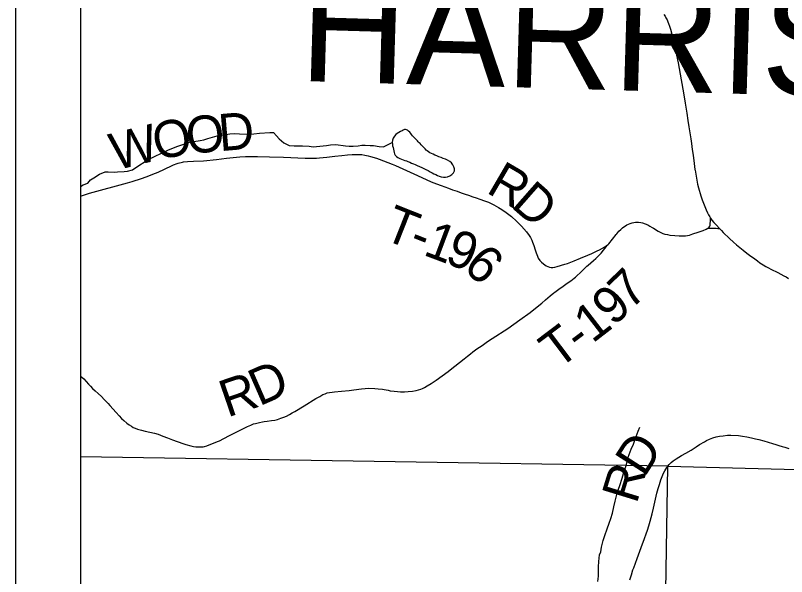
# Model space of a CAD drawing. Extents: x -19.9 to 41.9, y 0 to 32.3.
# Drawn here: x 2 to 3.184, y 16.729 to 17.59 of the extents above; entities that cross this region are included whole.
import ezdxf

# ---------------------------------------------------------------- set-up
doc = ezdxf.new("R2010")
doc.units = 0
for name, color, linetype in [('GM_X_Corporation', 7, 'Continuous'), ('GM_X_County_Road', 7, 'Continuous'), ('GM_X_County_Text', 7, 'Continuous'), ('GM_X_Minor_River', 7, 'Continuous'), ('GM_X_Township_Road', 7, 'Continuous'), ('GM_X_Township_Road_Text', 7, 'Continuous'), ('SH_Data', 7, 'Continuous')]:
    doc.layers.add(name, color=color, linetype=linetype)

msp = doc.modelspace()

# ---------------------------------------------------------------- linework, layer by layer
at = {"layer": 'GM_X_Corporation'}
for points in [[(2.1, 17.918), (2.1, 14.1), (8.9, 14.1), (8.9, 17.8974), (7.9072, 17.9171), (7.5529, 17.9242), (7.3858, 17.9277), (6.9468, 17.937), (6.7, 17.9422), (6.3069, 17.9505), (6.2497, 17.9517), (6.2397, 17.9517), (5.9048, 17.9534), (5.761, 17.9543), (5.4954, 17.9559), (5.0257, 17.9637), (5.0192, 17.8403), (4.9169, 17.8392), (4.2613, 17.8672), (3.984, 17.879), (3.7505, 17.884), (2.973, 17.9007), (2.4715, 17.9106)], [(2.1, 16.9124), (2.1, 15.8858), (2.9854, 15.8784), (3.0015, 16.8981)], [(3.0015, 16.8981), (4.0122, 16.8721), (3.9969, 15.8607), (2.9854, 15.8784)]]:
    msp.add_lwpolyline(points, close=True, dxfattribs=at)
msp.add_lwpolyline([(2.1, 17.918), (2.1, 14.1), (7.8246, 14.1), (7.8518, 15.3043), (7.854, 15.4058), (7.8702, 16.1679), (7.8776, 16.5173), (7.9012, 17.4524), (7.9072, 17.9171)], dxfattribs=at)
at = {"layer": 'GM_X_County_Road'}
msp.add_lwpolyline([(2.9956, 17.591), (2.9973, 17.5884), (2.9986, 17.586), (3.0004, 17.5828), (3.0017, 17.5801), (3.0028, 17.5774), (3.0043, 17.5731), (3.0058, 17.5684), (3.0071, 17.5632), (3.0092, 17.5543), (3.0138, 17.5334), (3.0173, 17.517), (3.0223, 17.4907), (3.0257, 17.471), (3.0283, 17.4552), (3.0307, 17.4396), (3.0325, 17.4286), (3.0339, 17.4187), (3.0348, 17.4126), (3.0368, 17.4003), (3.0379, 17.3931), (3.0392, 17.3842), (3.0404, 17.3751), (3.0421, 17.3627), (3.0433, 17.3534), (3.0434, 17.3524), (3.0466, 17.334), (3.0472, 17.3306), (3.0486, 17.3252), (3.0523, 17.313), (3.0544, 17.3069), (3.0574, 17.299), (3.0605, 17.2913), (3.0627, 17.2866), (3.0643, 17.2835), (3.0659, 17.2808), (3.0673, 17.2787), (3.0694, 17.2755), (3.0723, 17.272), (3.0756, 17.2681), (3.0809, 17.2626), (3.0839, 17.2595), (3.0868, 17.2566), (3.0964, 17.2473), (3.1026, 17.2416), (3.1072, 17.2377), (3.1172, 17.2295), (3.123, 17.225), (3.129, 17.2205), (3.133, 17.2176), (3.1392, 17.213), (3.1431, 17.2102), (3.148, 17.207), (3.1523, 17.2044), (3.156, 17.2025), (3.1598, 17.2005), (3.1705, 17.1951), (3.1752, 17.1926), (3.1796, 17.1902), (3.1832, 17.1883), (3.1868, 17.1862)], dxfattribs=at)
at = {"layer": 'GM_X_Minor_River'}
for points in [[(2.1, 17.3273), (2.1042, 17.3295), (2.111, 17.3322), (2.1151, 17.3373), (2.1203, 17.3404), (2.1293, 17.3462), (2.1376, 17.3498), (2.1425, 17.3495), (2.1516, 17.3492), (2.1569, 17.3497), (2.1668, 17.3502), (2.172, 17.3507), (2.1796, 17.3527), (2.1848, 17.3566), (2.204, 17.3687), (2.2341, 17.3829), (2.2427, 17.3864), (2.2495, 17.3892), (2.2672, 17.3952), (2.2834, 17.3977), (2.2895, 17.399), (2.2955, 17.401), (2.3098, 17.405), (2.3163, 17.4062), (2.3291, 17.408), (2.3371, 17.4085), (2.3439, 17.4078), (2.3564, 17.4076), (2.3662, 17.4081), (2.3749, 17.409), (2.3904, 17.41)], [(2.3904, 17.41), (2.3961, 17.4101), (2.4007, 17.4052), (2.405, 17.4004), (2.4119, 17.394), (2.4202, 17.3899), (2.4282, 17.3897), (2.4407, 17.3895), (2.4509, 17.3889), (2.457, 17.3882), (2.4623, 17.3887), (2.4672, 17.3891), (2.4774, 17.39), (2.4835, 17.3909), (2.4918, 17.3914), (2.5066, 17.3897), (2.5123, 17.3891), (2.5187, 17.3892), (2.5263, 17.3897), (2.5316, 17.3905), (2.5372, 17.3906), (2.5448, 17.3903), (2.5497, 17.39), (2.5585, 17.3886), (2.5649, 17.3883), (2.5786, 17.3948)], [(2.9456, 16.9243), (2.9489, 16.9316), (2.9529, 16.9434), (2.9562, 16.9515), (2.9584, 16.9576)], [(2.8944, 16.7209), (2.8951, 16.7293), (2.895, 16.735), (2.8953, 16.7434), (2.8959, 16.7518), (2.8969, 16.7617), (2.8987, 16.7667), (2.8997, 16.7739), (2.9022, 16.7839), (2.9048, 16.7915), (2.9084, 16.8019), (2.9117, 16.8107), (2.9139, 16.8176), (2.9168, 16.826), (2.9185, 16.8355), (2.9207, 16.8443), (2.9246, 16.8585), (2.9279, 16.8684), (2.9315, 16.8795), (2.9337, 16.8868), (2.938, 16.9006), (2.9409, 16.912), (2.9456, 16.9243)]]:
    msp.add_lwpolyline(points, dxfattribs=at)
for points in [[(2.5805, 17.3846), (2.5832, 17.3751), (2.5927, 17.369), (2.6026, 17.3656), (2.6137, 17.3607), (2.627, 17.355), (2.64, 17.3481), (2.6507, 17.3432), (2.6636, 17.342), (2.6739, 17.3512), (2.6697, 17.3633), (2.6567, 17.3702), (2.6438, 17.3755), (2.6342, 17.3804), (2.6213, 17.393), (2.6098, 17.4051), (2.5972, 17.4146), (2.5937, 17.4126)], [(2.5937, 17.4126), (2.5839, 17.407), (2.5786, 17.3948), (2.5805, 17.3846)]]:
    msp.add_spline(points, degree=3, dxfattribs=at)
at = {"layer": 'GM_X_Township_Road'}
for points in [[(2.1, 17.3122), (2.1139, 17.3169), (2.1721, 17.3328), (2.1793, 17.3349), (2.1934, 17.3395), (2.2005, 17.342), (2.2153, 17.3476), (2.2194, 17.3494), (2.2396, 17.3588), (2.2429, 17.3603), (2.2481, 17.3623), (2.25, 17.3629), (2.2565, 17.3645), (2.258, 17.3648), (2.2642, 17.3653), (2.2734, 17.3659), (2.2887, 17.3668), (2.3085, 17.3686), (2.324, 17.3705), (2.3342, 17.3715), (2.3443, 17.3726), (2.3531, 17.3731), (2.364, 17.3734), (2.3718, 17.3732), (2.3903, 17.3729), (2.4114, 17.3723), (2.445, 17.3706), (2.4497, 17.3705), (2.4559, 17.3705), (2.4622, 17.3708), (2.467, 17.3712), (2.4781, 17.3723), (2.4906, 17.3737), (2.5011, 17.3748), (2.5098, 17.3757), (2.5168, 17.3763), (2.5228, 17.3765), (2.5318, 17.3761), (2.5365, 17.3755), (2.5415, 17.3744), (2.5453, 17.3734), (2.5542, 17.3705), (2.5584, 17.369), (2.5782, 17.3614), (2.5834, 17.3592), (2.6171, 17.3441), (2.6385, 17.3346), (2.6464, 17.3312), (2.6535, 17.3285), (2.6647, 17.3244), (2.6709, 17.3223), (2.6781, 17.3198), (2.6842, 17.3177), (2.6904, 17.3156), (2.6955, 17.3139), (2.7024, 17.3115), (2.7076, 17.3097), (2.713, 17.3078), (2.72, 17.3053), (2.7262, 17.3029), (2.7304, 17.3012), (2.7344, 17.2993), (2.7382, 17.2972), (2.7417, 17.2949), (2.7467, 17.2919), (2.7536, 17.2871), (2.7615, 17.2813), (2.7695, 17.2741), (2.777, 17.2662), (2.7846, 17.2578), (2.7889, 17.2521), (2.7907, 17.249), (2.7926, 17.245), (2.794, 17.2416), (2.7961, 17.2364), (2.7981, 17.23), (2.7993, 17.2256), (2.8013, 17.2204), (2.8028, 17.2172), (2.805, 17.2137), (2.8075, 17.2108), (2.8105, 17.2083), (2.8146, 17.2055), (2.8172, 17.2044), (2.82, 17.2035), (2.8224, 17.2031), (2.8249, 17.203), (2.828, 17.2034), (2.8318, 17.2043), (2.8435, 17.2078), (2.8474, 17.2091), (2.858, 17.2131), (2.8678, 17.217), (2.8788, 17.2217), (2.8851, 17.2244), (2.8929, 17.2282), (2.8968, 17.2302), (2.9051, 17.2348), (2.9077, 17.2366), (2.9099, 17.2381), (2.9106, 17.2388), (2.9111, 17.2394), (2.9222, 17.2533), (2.9234, 17.2547), (2.9266, 17.2584), (2.9296, 17.2614), (2.932, 17.2636), (2.9343, 17.2655), (2.9365, 17.2669), (2.9385, 17.2681), (2.944, 17.2704), (2.9468, 17.2713), (2.9494, 17.2719), (2.9522, 17.2722), (2.9546, 17.2723), (2.9568, 17.2722), (2.9601, 17.2718), (2.9627, 17.2712), (2.967, 17.2697), (2.9708, 17.2681), (2.974, 17.2665), (2.9774, 17.2645), (2.9795, 17.2632), (2.9868, 17.2586), (2.9898, 17.257), (2.9939, 17.2553), (2.9971, 17.2542), (3.0011, 17.2533), (3.0049, 17.2526), (3.0122, 17.2518), (3.0191, 17.2514), (3.029, 17.2516), (3.0317, 17.252), (3.0347, 17.2527), (3.04, 17.2543), (3.0484, 17.2572), (3.0558, 17.2599), (3.0607, 17.2618), (3.0633, 17.2631), (3.0641, 17.2636), (3.0653, 17.265), (3.066, 17.2665), (3.0664, 17.2678), (3.0667, 17.2699), (3.0671, 17.2747), (3.0673, 17.2787)], [(3.0633, 17.2631), (3.0648, 17.2632), (3.0678, 17.2634), (3.0738, 17.2633), (3.076, 17.2632), (3.0785, 17.2629), (3.0809, 17.2626)], [(2.5911, 17.0123), (2.5973, 17.0122), (2.6032, 17.0125), (2.6094, 17.0132), (2.6155, 17.0143), (2.6188, 17.0151), (2.6222, 17.0162), (2.625, 17.0172), (2.6279, 17.0186), (2.6323, 17.0211), (2.6383, 17.0249), (2.6459, 17.03), (2.6642, 17.0434), (2.6702, 17.0478), (2.6744, 17.0512), (2.6888, 17.0629), (2.6939, 17.0668), (2.6987, 17.0705), (2.7025, 17.0735), (2.7085, 17.0778), (2.7167, 17.0834), (2.725, 17.0891), (2.7321, 17.094), (2.756, 17.1095), (2.7744, 17.1223), (2.7904, 17.134), (2.7936, 17.1365), (2.8081, 17.1483), (2.814, 17.1533), (2.821, 17.1592), (2.8266, 17.1639), (2.8281, 17.1651), (2.8341, 17.1695), (2.8407, 17.1741), (2.8473, 17.1787), (2.854, 17.1834), (2.8555, 17.1846), (2.8578, 17.1864), (2.8598, 17.1882), (2.8618, 17.19), (2.8674, 17.1954), (2.8725, 17.2004), (2.8773, 17.2049), (2.8791, 17.2066), (2.8876, 17.2135), (2.8911, 17.2166), (2.8943, 17.2198), (2.8969, 17.2224), (2.8993, 17.2251), (2.9087, 17.2366), (2.9099, 17.2381)], [(2.1, 17.0363), (2.1022, 17.0346), (2.105, 17.0318), (2.1124, 17.0239), (2.1152, 17.0209), (2.1185, 17.0174), (2.1225, 17.0138), (2.127, 17.0095), (2.1322, 17.0047), (2.1363, 17.0005), (2.1398, 16.9967), (2.1425, 16.9939), (2.145, 16.9912), (2.1545, 16.9804), (2.1593, 16.9751), (2.163, 16.9713), (2.1666, 16.968), (2.1713, 16.9642), (2.1747, 16.9616), (2.1783, 16.9591), (2.1809, 16.9575), (2.1839, 16.9562), (2.1874, 16.955), (2.1935, 16.9534), (2.1991, 16.9519), (2.2062, 16.9501), (2.2135, 16.9484), (2.2192, 16.9469), (2.2261, 16.9442), (2.2337, 16.9413), (2.241, 16.9385), (2.2572, 16.9327), (2.2614, 16.9313), (2.2694, 16.9292), (2.2733, 16.9284), (2.2769, 16.9278), (2.2802, 16.9275), (2.2831, 16.9274), (2.2859, 16.9275), (2.2882, 16.9278), (2.2905, 16.9283), (2.2939, 16.9293), (2.3103, 16.9356), (2.3134, 16.937), (2.3276, 16.9443), (2.3565, 16.9587), (2.3616, 16.9611), (2.3656, 16.9627), (2.3685, 16.9636), (2.3745, 16.9652), (2.3794, 16.9661), (2.3821, 16.9665), (2.3863, 16.9672), (2.3932, 16.968), (2.3982, 16.9688), (2.4022, 16.9698), (2.4075, 16.9715), (2.412, 16.973), (2.4161, 16.9748), (2.4206, 16.9772), (2.4249, 16.9796), (2.4288, 16.9819), (2.4431, 16.9906), (2.4611, 17.0016), (2.4672, 17.0051), (2.4721, 17.0077), (2.4756, 17.0092), (2.4788, 17.0103), (2.482, 17.011), (2.4861, 17.0117), (2.49, 17.0122), (2.5005, 17.0131), (2.5124, 17.0143), (2.5197, 17.0153), (2.5311, 17.0167), (2.5372, 17.0173), (2.5419, 17.0176), (2.5516, 17.0173), (2.557, 17.0168), (2.5636, 17.0159), (2.5662, 17.0155), (2.5693, 17.015), (2.5722, 17.0145), (2.5754, 17.0138), (2.5814, 17.013), (2.5864, 17.0126), (2.5911, 17.0123)], [(2.9435, 16.7236), (2.9459, 16.7314), (2.9481, 16.7389), (2.9492, 16.742), (2.9545, 16.7565), (2.9607, 16.7732), (2.9658, 16.7868), (2.9683, 16.794), (2.9703, 16.7999), (2.9724, 16.8065), (2.9746, 16.8135), (2.9762, 16.819), (2.9776, 16.8246), (2.9797, 16.8336), (2.9825, 16.8471), (2.9848, 16.8566), (2.9869, 16.8639), (2.9886, 16.8696), (2.991, 16.8769), (2.9929, 16.882), (2.995, 16.887), (2.997, 16.8907), (3.0002, 16.896), (3.0038, 16.9005), (3.0066, 16.9034), (3.0099, 16.9061), (3.0146, 16.909), (3.0228, 16.9141), (3.0291, 16.9177), (3.0377, 16.9227), (3.0451, 16.9275), (3.0505, 16.9312), (3.0577, 16.9354), (3.0611, 16.9373), (3.0654, 16.9393), (3.0706, 16.9413), (3.0761, 16.943), (3.0812, 16.944), (3.0865, 16.9447), (3.0934, 16.9453), (3.0982, 16.9455), (3.1101, 16.945), (3.1165, 16.9441), (3.1231, 16.9429), (3.1299, 16.9416), (3.1362, 16.9401), (3.1415, 16.9388), (3.1492, 16.9367), (3.1557, 16.9349), (3.1621, 16.933), (3.1677, 16.9313), (3.1723, 16.9299), (3.1773, 16.9283), (3.1811, 16.927), (3.1873, 16.9249)]]:
    msp.add_lwpolyline(points, dxfattribs=at)
at = {"layer": 'SH_Data'}
for p, q in [((2, 21), (2, 14)), ((2.1, 20.9), (2.1, 14.1))]:
    msp.add_line(p, q, dxfattribs=at)

# ---------------------------------------------------------------- texts
at = {"layer": 'GM_X_County_Text'}
msp.add_text('HARRISON COUNTY', height=0.170455, rotation=358.3166, dxfattribs=at).set_placement((2.4348, 17.4893))
at = {"layer": 'GM_X_Township_Road_Text'}
for s, rotation, p in [('D', 4.7264, (2.3138, 17.3813)), ('O', 11.5493, (2.2168, 17.3672)), ('O', 4.9749, (2.2641, 17.377)), ('W', 13.843, (2.1534, 17.3516)), ('R', 329.7207, (2.7211, 17.3189)), ('D', 318.6756, (2.7591, 17.297)), ('T', 338.4071, (2.562, 17.2474)), ('1', 339.3824, (2.6243, 17.2228)), ('-', 338.5705, (2.6017, 17.2317)), ('9', 339.7078, (2.6573, 17.2104)), ('6', 318.3652, (2.6854, 17.2011)), ('7', 44.6587, (2.9444, 17.1361)), ('9', 43.8963, (2.9186, 17.1113)), ('1', 37.676, (2.8858, 17.0855)), ('T', 37.0593, (2.8328, 17.0454)), ('-', 37.173, (2.8668, 17.0711)), ('D', 23.6916, (2.3742, 16.9894)), ('R', 18.9527, (2.3253, 16.9724)), ('D', 57.4042, (2.9656, 16.8796)), ('R', 72.9, (2.9536, 16.8387))]:
    msp.add_text(s, height=0.0568, rotation=rotation, dxfattribs=at).set_placement(p)

doc.saveas('drawing.dxf')
